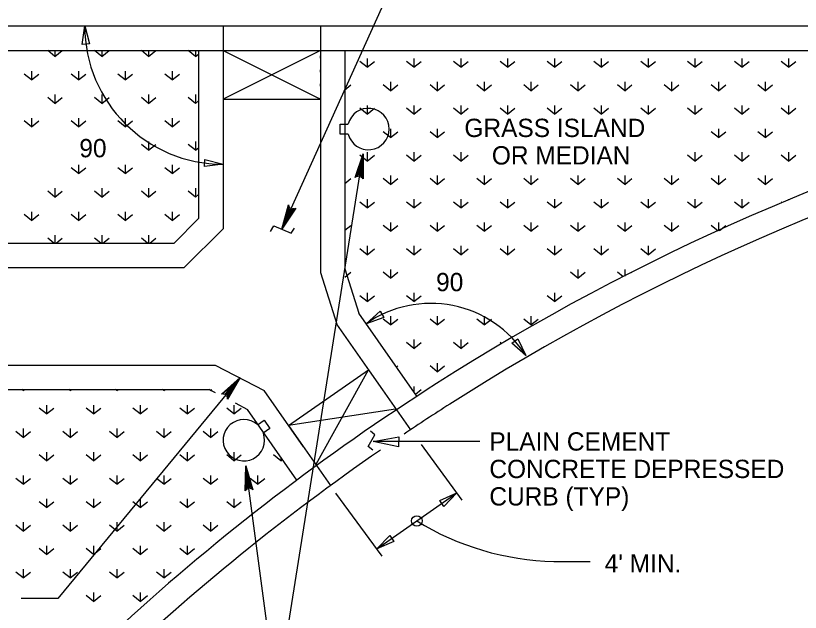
# Model space of a CAD drawing. Extents: x -344 to 940, y 22 to 1233.
# Drawn here: x 481.8 to 610.5, y 128.6 to 226.4 of the extents above; entities that cross this region are included whole.
import ezdxf

# ---------------------------------------------------------------- set-up
doc = ezdxf.new("R2010")
doc.units = 0
for name, color, linetype in [('1', 7, 'Continuous'), ('2', 7, 'Continuous'), ('Default', 7, 'Continuous')]:
    doc.layers.add(name, color=color, linetype=linetype)

msp = doc.modelspace()

# ---------------------------------------------------------------- linework, layer by layer
at = {"layer": '1'}
for points in [[(523.61, 190.98), (524.19, 191.89), (527.03, 190.71), (527.56, 191.53)], [(540.43, 155.12), (539.66, 155.75), (540.74, 157.64), (540, 158.28)]]:
    msp.add_lwpolyline(points, dxfattribs=at)
msp.add_circle((547.62, 143.54), 0.864, dxfattribs=at)
at = {"layer": '2'}
for p, q in [((515.76, 220.69), (531.84, 212.68)), ((531.72, 220.59), (515.84, 212.68)), ((535.07, 206.95), (535.07, 208.6)), ((535.07, 208.6), (536.37, 208.6)), ((536.37, 206.95), (535.07, 206.95)), ((524.67, 114.65), (538.81, 203.71)), ((531.11, 152.82), (539.71, 168.33)), ((544.15, 161.87), (526.59, 159.17)), ((521.52, 159.31), (522.6, 160.04)), ((522.6, 160.04), (523.53, 158.67)), ((523.53, 158.67), (522.45, 157.94)), ((524.67, 114.65), (519.57, 152.56))]:
    msp.add_line(p, q, dxfattribs=at)
for points in [[(537.72, 199.98), (538.02, 200.07), (538.81, 203.71), (537.72, 199.98), (537.53, 199.81), (538.81, 203.71), (538.41, 200.02), (538.66, 199.84), (538.81, 203.71), (538.81, 199.6), (538.66, 199.84)], [(527.53, 194.69), (527.22, 194.68), (525.5, 191.37), (527.53, 194.69), (527.77, 194.8), (525.5, 191.37), (526.86, 194.83), (526.66, 195.07), (525.5, 191.37), (526.58, 195.34), (526.66, 195.07)], [(515.83, 164.36), (516.13, 164.3), (518.66, 167.03), (515.83, 164.36), (515.57, 164.32), (518.66, 167.03), (516.43, 164.05), (516.56, 163.77), (518.66, 167.03), (516.57, 163.49), (516.56, 163.77)], [(519.61, 148.67), (519.87, 148.85), (519.57, 152.56), (519.61, 148.67), (519.47, 148.45), (519.57, 152.56), (520.25, 148.9), (520.54, 148.81), (519.57, 152.56), (520.75, 148.62), (520.54, 148.81)]]:
    msp.add_lwpolyline(points, dxfattribs=at)
for centre, start, end in [((539.67, 207.78), 194.1014, 165.8986), ((519.26, 156.77), 48.2263, 20.0236)]:
    msp.add_arc(centre, 3.4, start, end, dxfattribs=at)
at = {"layer": 'Default'}
for p, q in [((525.5, 191.37), (548.63, 242.69)), ((452.2, 224.68), (656.79, 224.68)), ((515.84, 224.68), (515.84, 191.43)), ((531.84, 224.68), (531.84, 212.68)), ((452.2, 220.68), (656.79, 220.68)), ((488.29, 219.67), (487.09, 220.63)), ((488.29, 220.68), (488.29, 219.67)), ((488.29, 219.67), (489.49, 220.63)), ((495.97, 219.67), (494.77, 220.63)), ((495.97, 220.68), (495.97, 219.67)), ((495.97, 219.67), (497.17, 220.63)), ((503.65, 219.67), (502.45, 220.63)), ((503.65, 220.68), (503.65, 219.67)), ((503.65, 219.67), (504.85, 220.63)), ((511.33, 219.67), (510.13, 220.63)), ((511.33, 220.68), (511.33, 219.67)), ((511.33, 219.67), (511.84, 220.07)), ((511.84, 220.68), (511.84, 193.09)), ((515.84, 220.68), (515.84, 212.68)), ((535.84, 220.68), (535.84, 184.87)), ((539.46, 217.9), (538.26, 218.86)), ((539.46, 219.34), (539.46, 217.9)), ((539.46, 217.9), (540.66, 218.86)), ((547.14, 217.9), (545.94, 218.86)), ((547.14, 219.34), (547.14, 217.9)), ((547.14, 217.9), (548.34, 218.86)), ((554.82, 217.9), (553.62, 218.86)), ((554.82, 219.34), (554.82, 217.9)), ((554.82, 217.9), (556.02, 218.86)), ((562.5, 217.9), (561.3, 218.86)), ((562.5, 219.34), (562.5, 217.9)), ((562.5, 217.9), (563.7, 218.86)), ((570.18, 217.9), (568.98, 218.86)), ((570.18, 219.34), (570.18, 217.9)), ((570.18, 217.9), (571.38, 218.86)), ((577.86, 217.9), (576.66, 218.86)), ((577.86, 219.34), (577.86, 217.9)), ((577.86, 217.9), (579.06, 218.86)), ((585.54, 217.9), (584.34, 218.86)), ((585.54, 219.34), (585.54, 217.9)), ((585.54, 217.9), (586.74, 218.86)), ((593.22, 217.9), (592.02, 218.86)), ((593.22, 219.34), (593.22, 217.9)), ((593.22, 217.9), (594.42, 218.86)), ((600.9, 217.9), (599.7, 218.86)), ((600.9, 219.34), (600.9, 217.9)), ((600.9, 217.9), (602.1, 218.86)), ((608.58, 217.9), (607.38, 218.86)), ((608.58, 219.34), (608.58, 217.9)), ((608.58, 217.9), (609.78, 218.86)), ((484.45, 215.83), (483.25, 216.79)), ((484.45, 217.27), (484.45, 215.83)), ((484.45, 215.83), (485.65, 216.79)), ((492.13, 215.83), (490.93, 216.79)), ((492.13, 217.27), (492.13, 215.83)), ((492.13, 215.83), (493.33, 216.79)), ((499.81, 215.83), (498.61, 216.79)), ((499.81, 217.27), (499.81, 215.83)), ((499.81, 215.83), (501.01, 216.79)), ((507.49, 215.83), (506.29, 216.79)), ((507.49, 217.27), (507.49, 215.83)), ((507.49, 215.83), (508.69, 216.79)), ((531.84, 216.68), (531.84, 184.25)), ((535.84, 214.23), (536.82, 215.02)), ((543.3, 214.06), (542.1, 215.02)), ((543.3, 215.5), (543.3, 214.06)), ((543.3, 214.06), (544.5, 215.02)), ((550.98, 214.06), (549.78, 215.02)), ((550.98, 215.5), (550.98, 214.06)), ((550.98, 214.06), (552.18, 215.02)), ((558.66, 214.06), (557.46, 215.02)), ((558.66, 215.5), (558.66, 214.06)), ((558.66, 214.06), (559.86, 215.02)), ((566.34, 214.06), (565.14, 215.02)), ((566.34, 215.5), (566.34, 214.06)), ((566.34, 214.06), (567.54, 215.02)), ((574.02, 214.06), (572.82, 215.02)), ((574.02, 215.5), (574.02, 214.06)), ((574.02, 214.06), (575.22, 215.02)), ((581.7, 214.06), (580.5, 215.02)), ((581.7, 215.5), (581.7, 214.06)), ((581.7, 214.06), (582.9, 215.02)), ((589.38, 214.06), (588.18, 215.02)), ((589.38, 215.5), (589.38, 214.06)), ((589.38, 214.06), (590.58, 215.02)), ((597.06, 214.06), (595.86, 215.02)), ((597.06, 215.5), (597.06, 214.06)), ((597.06, 214.06), (598.26, 215.02)), ((604.74, 214.06), (603.54, 215.02)), ((604.74, 215.5), (604.74, 214.06)), ((604.74, 214.06), (605.94, 215.02)), ((488.29, 211.99), (487.09, 212.95)), ((488.29, 213.43), (488.29, 211.99)), ((488.29, 211.99), (489.49, 212.95)), ((495.97, 211.99), (494.77, 212.95)), ((495.97, 213.43), (495.97, 211.99)), ((495.97, 211.99), (497.17, 212.95)), ((503.65, 211.99), (502.45, 212.95)), ((503.65, 213.43), (503.65, 211.99)), ((503.65, 211.99), (504.85, 212.95)), ((511.33, 211.99), (510.13, 212.95)), ((511.33, 213.43), (511.33, 211.99)), ((511.33, 211.99), (511.84, 212.39)), ((515.84, 212.68), (531.84, 212.68)), ((539.46, 210.22), (538.26, 211.18)), ((539.46, 211.66), (539.46, 210.22)), ((539.46, 210.22), (540.66, 211.18)), ((547.14, 210.22), (545.94, 211.18)), ((547.14, 211.66), (547.14, 210.22)), ((547.14, 210.22), (548.34, 211.18)), ((554.82, 210.22), (553.62, 211.18)), ((554.82, 211.66), (554.82, 210.22)), ((554.82, 210.22), (556.02, 211.18)), ((562.5, 210.22), (561.3, 211.18)), ((562.5, 211.66), (562.5, 210.22)), ((562.5, 210.22), (563.7, 211.18)), ((570.18, 210.22), (568.98, 211.18)), ((570.18, 211.66), (570.18, 210.22)), ((570.18, 210.22), (571.38, 211.18)), ((577.86, 210.22), (576.66, 211.18)), ((577.86, 211.66), (577.86, 210.22)), ((577.86, 210.22), (579.06, 211.18)), ((585.54, 210.22), (584.34, 211.18)), ((585.54, 211.66), (585.54, 210.22)), ((585.54, 210.22), (586.74, 211.18)), ((593.22, 210.22), (592.02, 211.18)), ((593.22, 211.66), (593.22, 210.22)), ((593.22, 210.22), (594.42, 211.18)), ((600.9, 210.22), (599.7, 211.18)), ((600.9, 211.66), (600.9, 210.22)), ((600.9, 210.22), (602.1, 211.18)), ((608.58, 210.22), (607.38, 211.18)), ((608.58, 211.66), (608.58, 210.22)), ((608.58, 210.22), (609.78, 211.18)), ((484.45, 208.15), (483.25, 209.11)), ((484.45, 209.59), (484.45, 208.15)), ((484.45, 208.15), (485.65, 209.11)), ((492.13, 208.15), (490.93, 209.11)), ((492.13, 209.59), (492.13, 208.15)), ((492.13, 208.15), (493.33, 209.11)), ((499.81, 208.15), (498.61, 209.11)), ((499.81, 209.59), (499.81, 208.15)), ((499.81, 208.15), (501.01, 209.11)), ((507.49, 208.15), (506.29, 209.11)), ((507.49, 209.59), (507.49, 208.15)), ((507.49, 208.15), (508.69, 209.11)), ((543.3, 206.38), (542.1, 207.34)), ((543.3, 207.82), (543.3, 206.38)), ((543.3, 206.38), (544.5, 207.34)), ((550.98, 206.38), (549.78, 207.34)), ((550.98, 207.82), (550.98, 206.38)), ((550.98, 206.38), (552.18, 207.34)), ((597.06, 206.38), (595.86, 207.34)), ((597.06, 207.82), (597.06, 206.38)), ((597.06, 206.38), (598.26, 207.34)), ((604.74, 206.38), (603.54, 207.34)), ((604.74, 207.82), (604.74, 206.38)), ((604.74, 206.38), (605.94, 207.34)), ((503.65, 204.31), (502.45, 205.27)), ((503.65, 205.75), (503.65, 204.31)), ((503.65, 204.31), (504.85, 205.27)), ((511.33, 204.31), (510.13, 205.27)), ((511.33, 205.75), (511.33, 204.31)), ((511.33, 204.31), (511.84, 204.71)), ((539.46, 202.54), (538.26, 203.5)), ((539.46, 203.98), (539.46, 202.54)), ((539.46, 202.54), (540.66, 203.5)), ((547.14, 202.54), (545.94, 203.5)), ((547.14, 203.98), (547.14, 202.54)), ((547.14, 202.54), (548.34, 203.5)), ((554.82, 202.54), (553.62, 203.5)), ((554.82, 203.98), (554.82, 202.54)), ((554.82, 202.54), (556.02, 203.5)), ((593.22, 202.54), (592.02, 203.5)), ((593.22, 203.98), (593.22, 202.54)), ((593.22, 202.54), (594.42, 203.5)), ((600.9, 202.54), (599.7, 203.5)), ((600.9, 203.98), (600.9, 202.54)), ((600.9, 202.54), (602.1, 203.5)), ((608.58, 202.54), (607.38, 203.5)), ((608.58, 203.98), (608.58, 202.54)), ((608.58, 202.54), (609.78, 203.5)), ((492.13, 200.47), (490.93, 201.43)), ((492.13, 201.91), (492.13, 200.47)), ((492.13, 200.47), (493.33, 201.43)), ((499.81, 200.47), (498.61, 201.43)), ((499.81, 201.91), (499.81, 200.47)), ((499.81, 200.47), (501.01, 201.43)), ((507.49, 200.47), (506.29, 201.43)), ((507.49, 201.91), (507.49, 200.47)), ((507.49, 200.47), (508.69, 201.43)), ((535.84, 198.87), (536.82, 199.66)), ((543.3, 198.7), (542.1, 199.66)), ((543.3, 200.14), (543.3, 198.7)), ((543.3, 198.7), (544.5, 199.66)), ((550.98, 198.7), (549.78, 199.66)), ((550.98, 200.14), (550.98, 198.7)), ((550.98, 198.7), (552.18, 199.66)), ((558.66, 198.7), (557.46, 199.66)), ((558.66, 200.14), (558.66, 198.7)), ((558.66, 198.7), (559.86, 199.66)), ((566.34, 198.7), (565.14, 199.66)), ((566.34, 200.14), (566.34, 198.7)), ((566.34, 198.7), (567.54, 199.66)), ((574.02, 198.7), (572.82, 199.66)), ((574.02, 200.14), (574.02, 198.7)), ((574.02, 198.7), (575.22, 199.66)), ((581.7, 198.7), (580.5, 199.66)), ((581.7, 200.14), (581.7, 198.7)), ((581.7, 198.7), (582.9, 199.66)), ((589.38, 198.7), (588.18, 199.66)), ((589.38, 200.14), (589.38, 198.7)), ((589.38, 198.7), (590.58, 199.66)), ((597.06, 198.7), (595.86, 199.66)), ((597.06, 200.14), (597.06, 198.7)), ((597.06, 198.7), (598.26, 199.66)), ((604.74, 198.7), (603.54, 199.66)), ((604.74, 200.14), (604.74, 198.7)), ((604.74, 198.7), (605.94, 199.66)), ((488.29, 196.63), (487.09, 197.59)), ((488.29, 198.07), (488.29, 196.63)), ((488.29, 196.63), (489.49, 197.59)), ((495.97, 196.63), (494.77, 197.59)), ((495.97, 198.07), (495.97, 196.63)), ((495.97, 196.63), (497.17, 197.59)), ((503.65, 196.63), (502.45, 197.59)), ((503.65, 198.07), (503.65, 196.63)), ((503.65, 196.63), (504.85, 197.59)), ((511.33, 196.63), (510.13, 197.59)), ((511.33, 198.07), (511.33, 196.63)), ((511.33, 196.63), (511.84, 197.03)), ((539.46, 194.86), (538.26, 195.82)), ((539.46, 196.3), (539.46, 194.86)), ((539.46, 194.86), (540.66, 195.82)), ((547.14, 194.86), (545.94, 195.82)), ((547.14, 196.3), (547.14, 194.86)), ((547.14, 194.86), (548.34, 195.82)), ((554.82, 194.86), (553.62, 195.82)), ((554.82, 196.3), (554.82, 194.86)), ((554.82, 194.86), (556.02, 195.82)), ((562.5, 194.86), (561.3, 195.82)), ((562.5, 196.3), (562.5, 194.86)), ((562.5, 194.86), (563.7, 195.82)), ((570.18, 194.86), (568.98, 195.82)), ((570.18, 196.3), (570.18, 194.86)), ((570.18, 194.86), (571.38, 195.82)), ((577.86, 194.86), (576.66, 195.82)), ((577.86, 196.3), (577.86, 194.86)), ((577.86, 194.86), (579.06, 195.82)), ((585.54, 194.86), (584.34, 195.82)), ((585.54, 196.3), (585.54, 194.86)), ((585.54, 194.86), (586.74, 195.82)), ((593.22, 194.86), (592.02, 195.82)), ((593.22, 196.3), (593.22, 194.86)), ((593.22, 194.86), (594.42, 195.82)), ((600.9, 194.86), (599.7, 195.82)), ((600.9, 196.3), (600.9, 194.86)), ((600.9, 194.86), (602.1, 195.82)), ((607.53, 195.7), (607.38, 195.82)), ((608.58, 196.3), (608.58, 196.12)), ((484.45, 192.79), (483.25, 193.75)), ((484.45, 194.23), (484.45, 192.79)), ((484.45, 192.79), (485.65, 193.75)), ((492.13, 192.79), (490.93, 193.75)), ((492.13, 194.23), (492.13, 192.79)), ((492.13, 192.79), (493.33, 193.75)), ((499.81, 192.79), (498.61, 193.75)), ((499.81, 194.23), (499.81, 192.79)), ((499.81, 192.79), (501.01, 193.75)), ((507.49, 192.79), (506.29, 193.75)), ((507.49, 194.23), (507.49, 192.79)), ((507.49, 192.79), (508.69, 193.75)), ((507.84, 189.09), (511.84, 193.09)), ((535.84, 191.19), (536.82, 191.98)), ((543.3, 191.02), (542.1, 191.98)), ((543.3, 192.46), (543.3, 191.02)), ((543.3, 191.02), (544.5, 191.98)), ((550.98, 191.02), (549.78, 191.98)), ((550.98, 192.46), (550.98, 191.02)), ((550.98, 191.02), (552.18, 191.98)), ((558.66, 191.02), (557.46, 191.98)), ((558.66, 192.46), (558.66, 191.02)), ((558.66, 191.02), (559.86, 191.98)), ((566.34, 191.02), (565.14, 191.98)), ((566.34, 192.46), (566.34, 191.02)), ((566.34, 191.02), (567.54, 191.98)), ((574.02, 191.02), (572.82, 191.98)), ((574.02, 192.46), (574.02, 191.02)), ((574.02, 191.02), (575.22, 191.98)), ((581.7, 191.02), (580.5, 191.98)), ((581.7, 192.46), (581.7, 191.02)), ((581.7, 191.02), (582.9, 191.98)), ((589.38, 191.02), (588.18, 191.98)), ((589.38, 192.46), (589.38, 191.02)), ((589.38, 191.02), (590.58, 191.98)), ((597.01, 191.06), (595.86, 191.98)), ((597.06, 192.46), (597.06, 191.08)), ((597.24, 191.17), (598.26, 191.98)), ((509.49, 185.09), (515.84, 191.43)), ((488.12, 189.09), (487.09, 189.91)), ((488.29, 190.39), (488.29, 189.09)), ((488.47, 189.09), (489.49, 189.91)), ((495.8, 189.09), (494.77, 189.91)), ((495.97, 190.39), (495.97, 189.09)), ((496.15, 189.09), (497.17, 189.91)), ((503.48, 189.09), (502.45, 189.91)), ((503.65, 190.39), (503.65, 189.09)), ((503.83, 189.09), (504.85, 189.91)), ((448.2, 189.09), (507.84, 189.09)), ((539.46, 187.18), (538.26, 188.14)), ((539.46, 188.62), (539.46, 187.18)), ((539.46, 187.18), (540.66, 188.14)), ((547.14, 187.18), (545.94, 188.14)), ((547.14, 188.62), (547.14, 187.18)), ((547.14, 187.18), (548.34, 188.14)), ((554.82, 187.18), (553.62, 188.14)), ((554.82, 188.62), (554.82, 187.18)), ((554.82, 187.18), (556.02, 188.14)), ((562.5, 187.18), (561.3, 188.14)), ((562.5, 188.62), (562.5, 187.18)), ((562.5, 187.18), (563.7, 188.14)), ((570.18, 187.18), (568.98, 188.14)), ((570.18, 188.62), (570.18, 187.18)), ((570.18, 187.18), (571.38, 188.14)), ((577.86, 187.18), (576.66, 188.14)), ((577.86, 188.62), (577.86, 187.18)), ((577.86, 187.18), (579.06, 188.14)), ((585.54, 187.18), (584.34, 188.14)), ((585.54, 188.62), (585.54, 187.18)), ((585.54, 187.18), (586.74, 188.14)), ((444.2, 185.09), (509.49, 185.09)), ((531.84, 184.25), (534.5, 175.8)), ((535.84, 184.87), (538.13, 177.59)), ((535.84, 183.51), (536.82, 184.3)), ((543.3, 183.34), (542.1, 184.3)), ((543.3, 184.78), (543.3, 183.34)), ((543.3, 183.34), (544.5, 184.3)), ((574.02, 183.34), (572.82, 184.3)), ((574.02, 184.78), (574.02, 183.34)), ((574.02, 183.34), (575.22, 184.3)), ((581.45, 183.53), (580.5, 184.3)), ((581.7, 184.78), (581.7, 183.66)), ((582.77, 184.2), (582.9, 184.3)), ((539.46, 179.5), (538.26, 180.46)), ((539.46, 180.94), (539.46, 179.5)), ((539.46, 179.5), (540.66, 180.46)), ((547.14, 179.5), (545.94, 180.46)), ((547.14, 180.94), (547.14, 179.5)), ((547.14, 179.5), (548.34, 180.46)), ((570.18, 179.5), (568.98, 180.46)), ((570.18, 180.94), (570.18, 179.5)), ((570.18, 179.5), (571.38, 180.46)), ((547.63, 163.98), (538.13, 177.59)), ((543.3, 175.66), (542.1, 176.62)), ((543.3, 177.1), (543.3, 175.66)), ((543.3, 175.66), (544.5, 176.62)), ((550.98, 175.66), (549.78, 176.62)), ((550.98, 177.1), (550.98, 175.66)), ((550.98, 175.66), (552.18, 176.62)), ((558.66, 175.66), (557.46, 176.62)), ((558.66, 177.1), (558.66, 175.66)), ((558.66, 175.66), (559.86, 176.62)), ((566.34, 175.66), (565.14, 176.62)), ((566.34, 177.1), (566.34, 175.66)), ((566.34, 175.66), (567.54, 176.62)), ((542.15, 164.85), (534.5, 175.8)), ((547.14, 171.82), (545.94, 172.78)), ((547.14, 173.26), (547.14, 171.82)), ((547.14, 171.82), (548.34, 172.78)), ((554.82, 171.82), (553.62, 172.78)), ((554.82, 173.26), (554.82, 171.82)), ((554.82, 171.82), (556.02, 172.78)), ((561.55, 172.58), (561.3, 172.78)), ((562.5, 173.26), (562.5, 173.15)), ((444.2, 169.09), (514.56, 169.09)), ((514.56, 169.09), (522.59, 164.9)), ((544.29, 168.77), (544.5, 168.94)), ((550.98, 167.98), (549.78, 168.94)), ((550.98, 169.42), (550.98, 167.98)), ((550.98, 167.98), (552.18, 168.94)), ((526.59, 159.17), (539.71, 168.33)), ((539.71, 168.33), (546.59, 158.49)), ((518.66, 167.03), (488.77, 130.81)), ((448.2, 165.09), (513.58, 165.09)), ((483.08, 164.92), (482.87, 165.09)), ((483.08, 165.09), (483.08, 164.92)), ((483.08, 164.92), (483.29, 165.09)), ((490.76, 164.92), (490.55, 165.09)), ((490.76, 165.09), (490.76, 164.92)), ((490.76, 164.92), (490.97, 165.09)), ((498.44, 164.92), (498.23, 165.09)), ((498.44, 165.09), (498.44, 164.92)), ((498.44, 164.92), (498.65, 165.09)), ((506.12, 164.92), (505.91, 165.09)), ((506.12, 165.09), (506.12, 164.92)), ((506.12, 164.92), (506.33, 165.09)), ((513.58, 165.09), (514.56, 164.58)), ((513.8, 164.92), (513.59, 165.09)), ((513.8, 165.09), (513.8, 164.92)), ((513.8, 164.92), (514.01, 165.09)), ((529.03, 155.68), (522.59, 164.9)), ((547.14, 165.58), (547.14, 164.69)), ((547.38, 164.34), (548.34, 165.1)), ((486.92, 162.52), (486.92, 161.08)), ((494.6, 162.52), (494.6, 161.08)), ((502.28, 162.52), (502.28, 161.08)), ((509.96, 162.52), (509.96, 161.08)), ((517.64, 162.52), (517.64, 161.08)), ((517.83, 162.88), (519.87, 161.81)), ((486.92, 161.08), (485.72, 162.04)), ((486.92, 161.08), (488.12, 162.04)), ((494.6, 161.08), (493.4, 162.04)), ((494.6, 161.08), (495.8, 162.04)), ((502.28, 161.08), (501.08, 162.04)), ((502.28, 161.08), (503.48, 162.04)), ((509.96, 161.08), (508.76, 162.04)), ((509.96, 161.08), (511.16, 162.04)), ((517.64, 161.08), (516.44, 162.04)), ((517.64, 161.08), (518.84, 162.04)), ((527.96, 150.23), (519.87, 161.81)), ((483.08, 158.68), (483.08, 157.24)), ((490.76, 158.68), (490.76, 157.24)), ((498.44, 158.68), (498.44, 157.24)), ((506.12, 158.68), (506.12, 157.24)), ((513.8, 158.68), (513.8, 157.24)), ((526.59, 159.17), (533.46, 149.33)), ((483.08, 157.24), (481.88, 158.2)), ((483.08, 157.24), (484.28, 158.2)), ((490.76, 157.24), (489.56, 158.2)), ((490.76, 157.24), (491.96, 158.2)), ((498.44, 157.24), (497.24, 158.2)), ((498.44, 157.24), (499.64, 158.2)), ((506.12, 157.24), (504.92, 158.2)), ((506.12, 157.24), (507.32, 158.2)), ((513.8, 157.24), (512.6, 158.2)), ((513.8, 157.24), (515, 158.2)), ((557.97, 156.55), (540.45, 156.55)), ((555.06, 146.92), (548.36, 156.07)), ((486.92, 154.84), (486.92, 153.4)), ((494.6, 154.84), (494.6, 153.4)), ((502.28, 154.84), (502.28, 153.4)), ((509.96, 154.84), (509.96, 153.4)), ((517.64, 154.84), (517.64, 153.4)), ((486.92, 153.4), (485.72, 154.36)), ((486.92, 153.4), (488.12, 154.36)), ((494.6, 153.4), (493.4, 154.36)), ((494.6, 153.4), (495.8, 154.36)), ((502.28, 153.4), (501.08, 154.36)), ((502.28, 153.4), (503.48, 154.36)), ((509.96, 153.4), (508.76, 154.36)), ((509.96, 153.4), (511.16, 154.36)), ((517.64, 153.4), (516.44, 154.36)), ((517.64, 153.4), (518.84, 154.36)), ((525.32, 153.4), (524.12, 154.36)), ((525.32, 154.01), (525.32, 153.4)), ((525.32, 153.4), (525.59, 153.62)), ((483.08, 151), (483.08, 149.56)), ((490.76, 151), (490.76, 149.56)), ((498.44, 151), (498.44, 149.56)), ((506.12, 151), (506.12, 149.56)), ((513.8, 151), (513.8, 149.56)), ((521.48, 151), (521.48, 149.56)), ((483.08, 149.56), (481.88, 150.52)), ((483.08, 149.56), (484.28, 150.52)), ((490.76, 149.56), (489.56, 150.52)), ((490.76, 149.56), (491.96, 150.52)), ((498.44, 149.56), (497.24, 150.52)), ((498.44, 149.56), (499.64, 150.52)), ((506.12, 149.56), (504.92, 150.52)), ((506.12, 149.56), (507.32, 150.52)), ((513.8, 149.56), (512.6, 150.52)), ((513.8, 149.56), (515, 150.52)), ((521.48, 149.56), (520.28, 150.52)), ((521.48, 149.56), (522.68, 150.52)), ((541.94, 137.75), (534.35, 148.12)), ((541.06, 138.96), (554.18, 148.13)), ((486.92, 145.72), (485.72, 146.68)), ((486.92, 147.16), (486.92, 145.72)), ((486.92, 145.72), (488.12, 146.68)), ((494.6, 145.72), (493.4, 146.68)), ((494.6, 147.16), (494.6, 145.72)), ((494.6, 145.72), (495.8, 146.68)), ((502.28, 145.72), (501.08, 146.68)), ((502.28, 147.16), (502.28, 145.72)), ((502.28, 145.72), (503.48, 146.68)), ((509.96, 145.72), (508.76, 146.68)), ((509.96, 147.16), (509.96, 145.72)), ((509.96, 145.72), (511.16, 146.68)), ((517.64, 145.72), (516.44, 146.68)), ((517.64, 147.16), (517.64, 145.72)), ((517.64, 145.72), (518.84, 146.68)), ((483.08, 141.88), (481.88, 142.84)), ((483.08, 143.32), (483.08, 141.88)), ((483.08, 141.88), (484.28, 142.84)), ((490.76, 141.88), (489.56, 142.84)), ((490.76, 143.32), (490.76, 141.88)), ((490.76, 141.88), (491.96, 142.84)), ((498.44, 141.88), (497.24, 142.84)), ((498.44, 143.32), (498.44, 141.88)), ((498.44, 141.88), (499.64, 142.84)), ((506.12, 141.88), (504.92, 142.84)), ((506.12, 143.32), (506.12, 141.88)), ((506.12, 141.88), (507.32, 142.84)), ((513.8, 141.88), (512.6, 142.84)), ((513.8, 143.32), (513.8, 141.88)), ((513.8, 141.88), (515, 142.84)), ((486.92, 138.04), (485.72, 139)), ((486.92, 139.48), (486.92, 138.04)), ((486.92, 138.04), (488.12, 139)), ((494.6, 138.04), (493.4, 139)), ((494.6, 139.48), (494.6, 138.04)), ((494.6, 138.04), (495.8, 139)), ((502.28, 138.04), (501.08, 139)), ((502.28, 139.48), (502.28, 138.04)), ((502.28, 138.04), (503.48, 139)), ((509.96, 138.04), (508.76, 139)), ((509.96, 139.48), (509.96, 138.04)), ((509.96, 138.04), (511.16, 139)), ((570.09, 136.91), (576.06, 136.91)), ((483.08, 134.2), (481.88, 135.16)), ((483.08, 135.64), (483.08, 134.2)), ((483.08, 134.2), (484.28, 135.16)), ((490.76, 134.2), (489.56, 135.16)), ((490.76, 135.64), (490.76, 134.2)), ((490.76, 134.2), (491.96, 135.16)), ((498.44, 134.2), (497.24, 135.16)), ((498.44, 135.64), (498.44, 134.2)), ((498.44, 134.2), (499.64, 135.16)), ((506.12, 134.2), (504.92, 135.16)), ((506.12, 135.64), (506.12, 134.2)), ((506.12, 134.2), (507.32, 135.16)), ((494.6, 130.36), (493.4, 131.32)), ((494.6, 131.8), (494.6, 130.36)), ((494.6, 130.36), (495.8, 131.32)), ((502.28, 130.36), (501.08, 131.32)), ((502.28, 131.8), (502.28, 130.36)), ((502.28, 130.36), (503.48, 131.32)), ((488.77, 130.81), (482.77, 130.81))]:
    msp.add_line(p, q, dxfattribs=at)
for points in [[(492.77, 221.65), (493.17, 224.68), (493.97, 221.73)], [(512.88, 202.81), (515.84, 202.02), (512.8, 201.62)], [(542.22, 176.87), (539.32, 175.87), (541.61, 177.9)], [(564.17, 173.41), (565.51, 170.66), (563.22, 172.68)], [(544.64, 155.67), (540.45, 156.55), (544.66, 157.35)], [(551.37, 146.9), (554.18, 148.13), (552.06, 145.92)], [(543.86, 140.19), (541.06, 138.96), (543.17, 141.17)]]:
    msp.add_lwpolyline(points, close=True, dxfattribs=at)
for centre, radius, start, end in [((515.84, 224.68), 22.67, 180, 270), ((532.29, 219.59), 0.517, 151.496, 208.504), ((532.29, 217.29), 0.517, 151.496, 180), ((532.29, 217.28), 0.517, 180, 208.504), ((532.29, 214.98), 0.517, 151.496, 208.504), ((532.29, 212.68), 0.517, 151.496, 180), ((753.46, -151.64), 376.8, 104.7063, 122.5261), ((753.46, -151.64), 372.8, 104.7063, 122.5261), ((549.92, 160.71), 18.49, 32.5261, 124.9342), ((753.46, -151.64), 376.8, 122.5261, 142.2884), ((753.46, -151.64), 372.8, 122.5261, 123.9004), ((753.46, -151.64), 372.8, 124.6158, 142.2884), ((571.07, 181.62), 44.72, 238.3693, 268.7424)]:
    msp.add_arc(centre, radius, start, end, dxfattribs=at)

# ---------------------------------------------------------------- texts
for s, p in [('GRASS ISLAND', (555.42, 206.47)), ('90', (492.28, 203.15)), ('OR MEDIAN', (559.92, 201.97)), ('90', (550.78, 181.2)), ('PLAIN CEMENT', (559.51, 155.07)), ('CONCRETE DEPRESSED', (559.51, 150.57)), ('CURB (TYP)', (559.51, 146.07)), ("4' MIN.", (578.42, 135.09))]:
    msp.add_text(s, height=3, dxfattribs=at).set_placement(p)

doc.saveas('drawing.dxf')
